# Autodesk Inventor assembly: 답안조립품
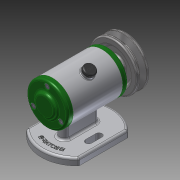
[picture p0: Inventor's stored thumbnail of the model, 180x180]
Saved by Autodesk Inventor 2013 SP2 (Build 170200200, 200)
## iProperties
Created: 2022-02
Part Number: 답안조립품
Document SubType Name: Assembly
Designer: a
Author: a
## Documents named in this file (14)
- C:\Users\a\Desktop\720206V1014\답안조립품.iam
- C:\Users\a\Desktop\720206V1014\본체.ipt
- C:\Users\a\Desktop\720206V1014\V벨트풀리.ipt
- C:\Users\a\Desktop\720206V1014\고무 캡.ipt
- C:\Users\a\Desktop\720206V1014\너트 M8.ipt
- C:\Users\a\Desktop\720206V1014\뒤커버.ipt
- C:\Users\a\Desktop\720206V1014\베어링 6002.ipt
- C:\Users\a\Desktop\720206V1014\볼트 M4 x 10.ipt
- C:\Users\a\Desktop\720206V1014\스프링와셔 8.ipt
- C:\Users\a\Desktop\720206V1014\앞커버.ipt
- C:\Users\a\Desktop\720206V1014\오일 실 15 x 25 x 7.ipt
- C:\Users\a\Desktop\720206V1014\축.ipt
- C:\Users\a\Desktop\720206V1014\키 3 x 3 x 12.ipt
- C:\Users\a\Desktop\720206V1014\평와셔 8 x 17.ipt
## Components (2 placed, 2 different names)
1. V벨트풀리:1
2. 고무 캡:1
